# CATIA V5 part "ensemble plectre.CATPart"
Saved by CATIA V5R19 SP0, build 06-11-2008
Part number: F2
Revision: ANY
Definition: UNKNOWN
Nomenclature: F2
Source: Unknown
Bounding box of the stored display mesh (mm): x -12.5 to 12.501, y -26.5 to 10.545, z -24.25 to 24.25
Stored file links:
  G:\project guitar elect\ensemble plectre.CATPart
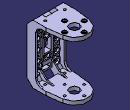
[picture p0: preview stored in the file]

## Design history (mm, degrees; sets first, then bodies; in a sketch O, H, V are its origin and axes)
Solid1: solid without history
Set1 "FaceKO#NONE#3497"
  DatumSurface1 "Sur3497_1"
  Line1 "Crv3497_1": stored without definition
Set2 "FaceKO#NONE#11526"
  DatumSurface2 "Sur11526_1"
  Line2 "Crv11526_1": stored without definition
Set3
  Sketch1 on face of Solid1, origin (0, -26.5, 0), H (1, 0, 0), V (0, 0, 1)
    circle A1 centre (8, 16) radius 1
    circle A2 centre (-8, 16) radius 1
    circle A3 centre (8, -16) radius 1
    circle A4 centre (-8, -16) radius 1
    circle A5 centre (8, 16) radius 1.4142
    circle A6 centre (-8, 16) radius 1.4142
    circle A7 centre (8, -16) radius 1.4142
    circle A8 centre (-8, -16) radius 1.4142
    radius A3 = 1
    radius A4 = 1
    radius A2 = 1
    radius A1 = 1
Body1 "Mirror6" (main body)
  Pad1: profile Sketch1, direction (0, 1, 0), length 2.5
